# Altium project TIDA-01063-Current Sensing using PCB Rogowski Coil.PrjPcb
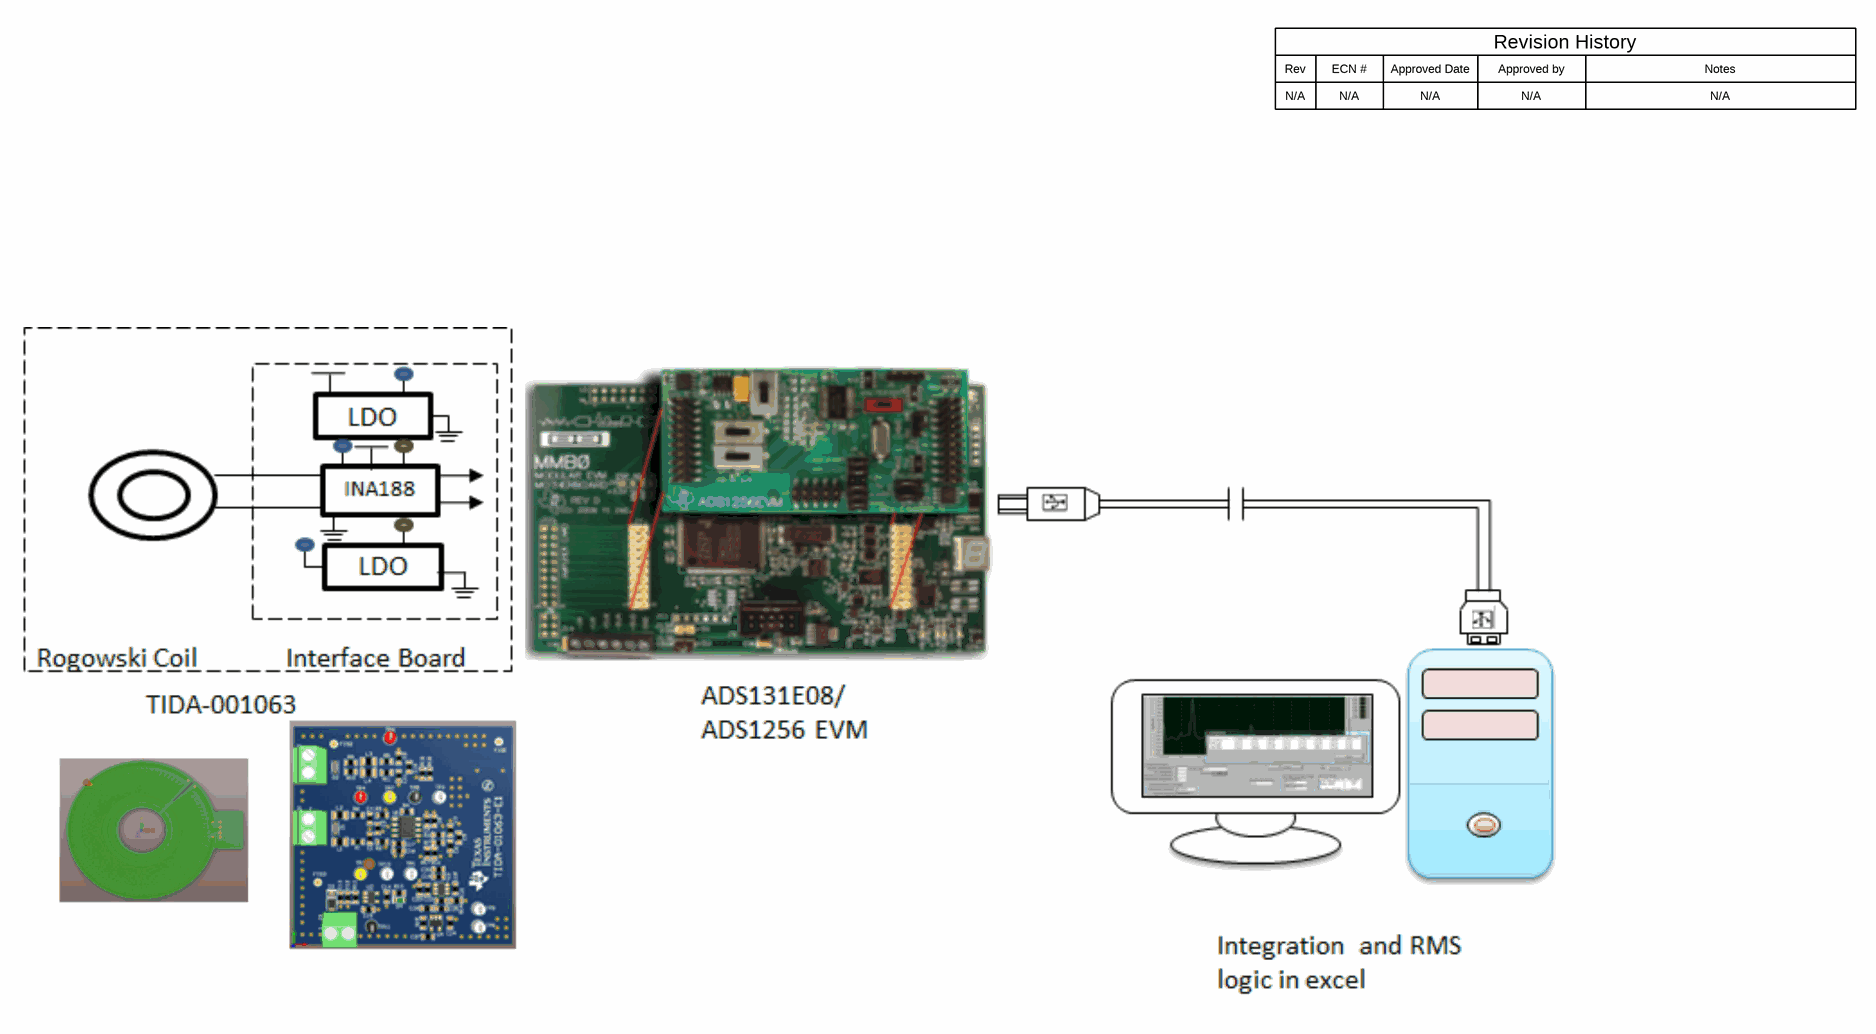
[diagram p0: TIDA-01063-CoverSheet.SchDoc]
TID: TIDA-01063; TechSupport: http://www.ti.com/support; SCH_Rev: E1; PRJ_Title: Current Sensing using PCB Rogowski Coil; PRJ_Number: TIDA-01063; PRJ_Engineer: Srinivasan Iyer; PRJ_Customer: Public Release; PCB_Rev: E1; PCB_Layout: Avinash N; EVM_Orderable: N/A; CopyrightYear: 2016
3 sheets, 86 parts. Net scope: global (net labels, ports and power ports of the same name join across sheets).
Board file: TIDA-01063-Interface Board.PcbDoc
Sheets:
  TIDA-01063-CoverSheet.SchDoc
  TIDA-01063-BlankSheet.SchDoc
  TIDA-01063_Hardware.SchDoc

## Sheet TIDA-01063-CoverSheet.SchDoc: Block Diagram
size 431 x 279 mm; Date: Not shown in title block; ApprovedBy: Not shown in title block; CheckedBy: Not shown in title block; Author: Not shown in title block; CompanyName: Not shown in title block; DrawnBy: Srinivasan Iyer; Engineer: Not shown in title block; Organization: Not shown in title block; Address1: Not shown in title block; Address2: Not shown in title block; Address3: Not shown in title block; Address4: Not shown in title block; DocumentNumber: 1; Revision: Use project parameter SCH_Rev; SheetNumber: 1; SheetTotal: 3; PageSetup: Record=PageOptions¦CenterHorizontal=True¦CenterVertical=True¦PrintScale=1.00¦XCorrection=1.00¦YCorrection=1.00¦PrintKind=0¦BorderSize=5000000¦LeftOffset=0¦BottomOffset=0¦Orientation=2¦PaperLength=1000¦PaperWidth=1000¦Scale=100¦PaperSource=15¦PrintQuality=600¦MediaType=1¦DitherType=10¦PaperKind=Letter¦PrintScaleMode=1

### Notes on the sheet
- Rev
- N/A
- ECN #
- Approved Date
- Approved by
- Revision History
- Notes

## Sheet TIDA-01063-BlankSheet.SchDoc: PCB Rogowski Coil Amplifier
size 431 x 279 mm; Date: Not shown in title block; ApprovedBy: Not shown in title block; CheckedBy: Not shown in title block; Author: Not shown in title block; CompanyName: Not shown in title block; DrawnBy: Srinivasan Iyer; Engineer: Not shown in title block; Organization: Not shown in title block; Address1: Not shown in title block; Address2: Not shown in title block; Address3: Not shown in title block; Address4: Not shown in title block; DocumentNumber: 1; Revision: Use project parameter SCH_Rev; SheetNumber: 2; SheetTotal: 3; PageSetup: Record=PageOptions¦CenterHorizontal=True¦CenterVertical=True¦PrintScale=1.00¦XCorrection=1.00¦YCorrection=1.00¦PrintKind=0¦BorderSize=5000000¦LeftOffset=0¦BottomOffset=0¦Orientation=2¦PaperLength=1000¦PaperWidth=1000¦Scale=100¦PaperSource=15¦PrintQuality=600¦MediaType=1¦DitherType=10¦PaperKind=Letter¦PrintScaleMode=1
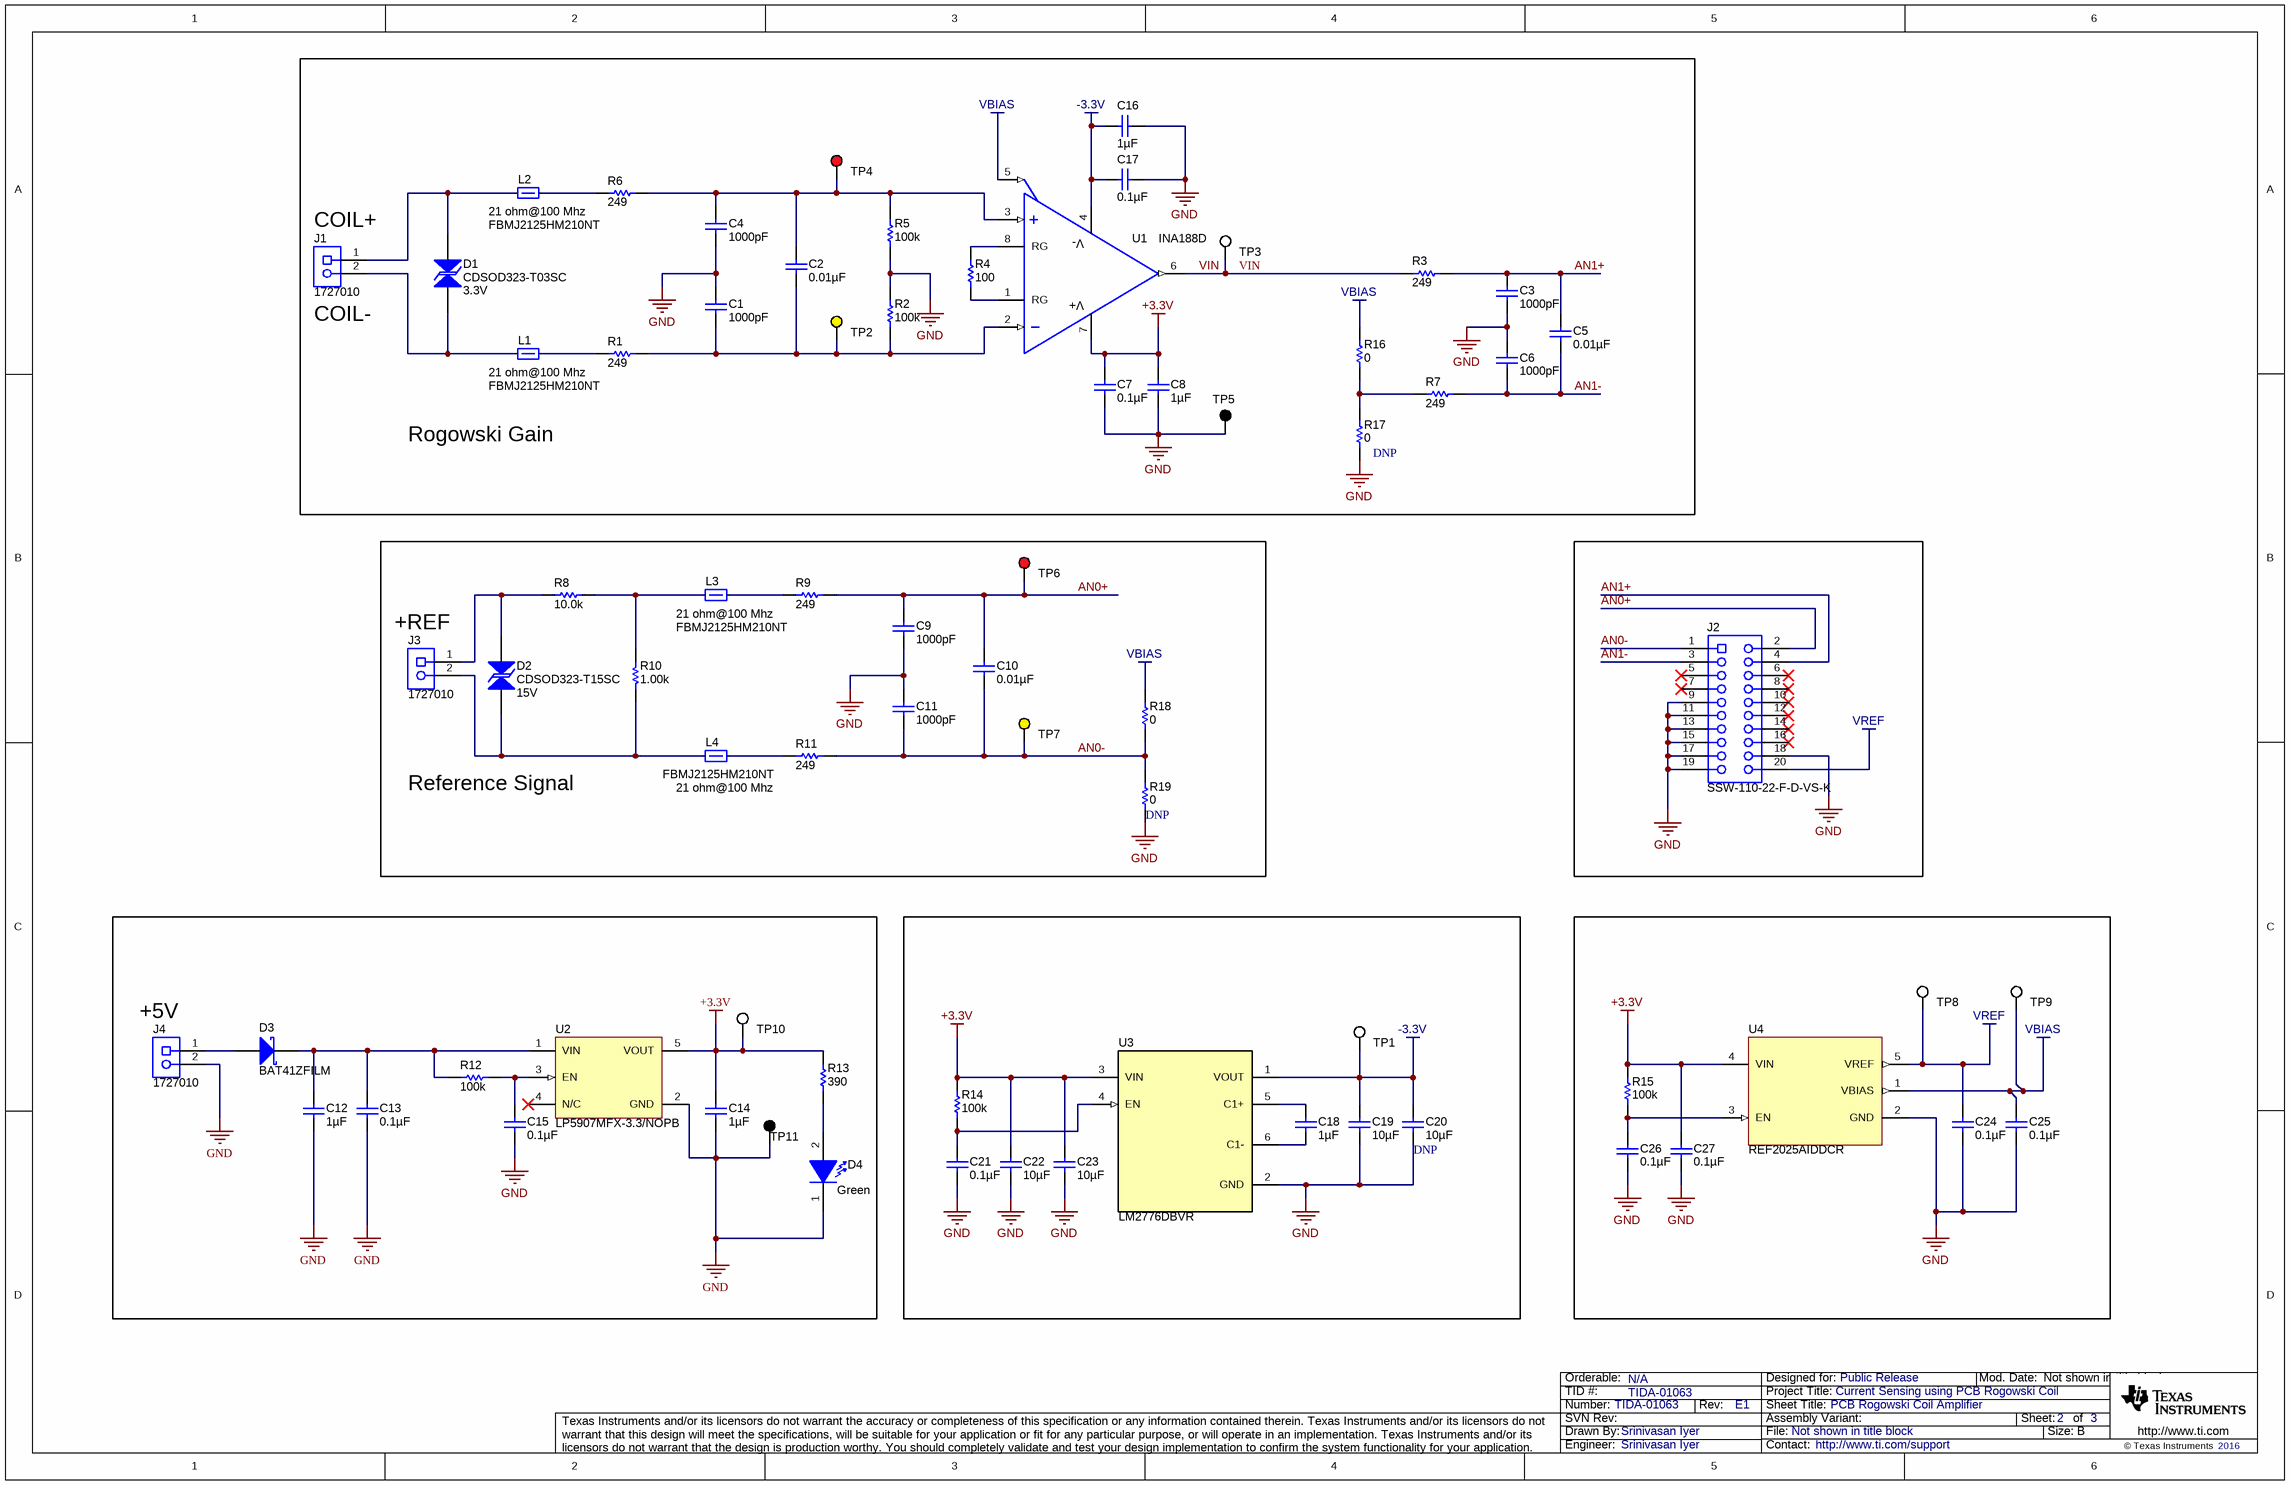
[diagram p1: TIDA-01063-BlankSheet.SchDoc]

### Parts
C1  ValueDisplayed: 1000pF  [0603]  (hidden comment: C0603X102K5RACTU)
C2  ValueDisplayed: 0.01µF  [0603]  (hidden comment: 06031C103JAT2A)
C3  ValueDisplayed: 1000pF  [0603]  (hidden comment: C0603X102K5RACTU)
C4  ValueDisplayed: 1000pF  [0603]  (hidden comment: C0603X102K5RACTU)
C5  ValueDisplayed: 0.01µF  [0603]  (hidden comment: 06031C103JAT2A)
C6  ValueDisplayed: 1000pF  [0603]  (hidden comment: C0603X102K5RACTU)
C7  ValueDisplayed: 0.1µF  [0603]  (hidden comment: CGA3E2X8R1E104K080AA)
C8  ValueDisplayed: 1µF  [0603]  (hidden comment: C1608X5R1C105K)
C9  ValueDisplayed: 1000pF  [0603]  (hidden comment: C0603X102K5RACTU)
C10  ValueDisplayed: 0.01µF  [0603]  (hidden comment: 06031C103JAT2A)
C11  ValueDisplayed: 1000pF  [0603]  (hidden comment: C0603X102K5RACTU)
C12  ValueDisplayed: 1µF  [0603]  (hidden comment: C1608X5R1C105K)
C13  ValueDisplayed: 0.1µF  [0603]  (hidden comment: CGA3E2X8R1E104K080AA)
C14  ValueDisplayed: 1µF  [0603]  (hidden comment: C1608X5R1C105K)
C15  ValueDisplayed: 0.1µF  [0603]  (hidden comment: CGA3E2X8R1E104K080AA)
C16  ValueDisplayed: 1µF  [0603]  (hidden comment: C1608X5R1C105K)
C17  ValueDisplayed: 0.1µF  [0603]  (hidden comment: CGA3E2X8R1E104K080AA)
C18  ValueDisplayed: 1µF  [0603]  (hidden comment: C1608X5R1C105K)
C19  ValueDisplayed: 10µF  [0603]  (hidden comment: C0603C106M9PACTU)
C20  ValueDisplayed: 10µF  [0603]  (hidden comment: C0603C106M9PACTU)
C21  ValueDisplayed: 0.1µF  [0603]  (hidden comment: CGA3E2X8R1E104K080AA)
C22  ValueDisplayed: 10µF  [0603]  (hidden comment: C0603C106M9PACTU)
C23  ValueDisplayed: 10µF  [0603]  (hidden comment: C0603C106M9PACTU)
C24  ValueDisplayed: 0.1µF  [0603]  (hidden comment: CGA3E2X8R1E104K080AA)
C25  ValueDisplayed: 0.1µF  [0603]  (hidden comment: CGA3E2X8R1E104K080AA)
C26  ValueDisplayed: 0.1µF  [0603]  (hidden comment: CGA3E2X8R1E104K080AA)
C27  ValueDisplayed: 0.1µF  [0603]  (hidden comment: CGA3E2X8R1E104K080AA)
D1  CDSOD323-T03SC  value 3.3V  [SOD-323-Bi]
D2  CDSOD323-T15SC  value 15V  [SOD-323-Bi]
D3  BAT41ZFILM  [SOD-123]
D4  value Green  [WL-SMCW_GREEN]  (hidden comment: 150060GS75000)
J1  1727010  [PhoenixConact_1727010]
J2  SSW-110-22-F-D-VS-K  [CONN_SSW-110-22-F-D-VS-K]
J3  1727010  [PhoenixConact_1727010]
J4  1727010  [PhoenixConact_1727010]
L1  value 21 ohm@100 Mhz  [0805_HV]  (hidden comment: FBMJ2125HM210NT)
L2  value 21 ohm@100 Mhz  [0805_HV]  (hidden comment: FBMJ2125HM210NT)
L3  value 21 ohm@100 Mhz  [0805_HV]  (hidden comment: FBMJ2125HM210NT)
L4  value 21 ohm@100 Mhz  [0805_HV]  (hidden comment: FBMJ2125HM210NT)
R1  ValueDisplayed: 249  [0603]  (hidden comment: RT0603BRD07249RL)
R2  ValueDisplayed: 100k  [0603]  (hidden comment: RC0603FR-07100KL)
R3  ValueDisplayed: 249  [0603]  (hidden comment: RT0603BRD07249RL)
R4  ValueDisplayed: 100  [0603]  (hidden comment: ERA-3AEB101V)
R5  ValueDisplayed: 100k  [0603]  (hidden comment: RC0603FR-07100KL)
R6  ValueDisplayed: 249  [0603]  (hidden comment: RT0603BRD07249RL)
R7  ValueDisplayed: 249  [0603]  (hidden comment: RT0603BRD07249RL)
R8  ValueDisplayed: 10.0k  [0603]  (hidden comment: RT0603DRE0710KL)
R9  ValueDisplayed: 249  [0603]  (hidden comment: RT0603BRD07249RL)
R10  ValueDisplayed: 1.00k  [0603]  (hidden comment: RT0603DRE071KL)
R11  ValueDisplayed: 249  [0603]  (hidden comment: RT0603BRD07249RL)
R12  ValueDisplayed: 100k  [0603]  (hidden comment: RC0603FR-07100KL)
R13  ValueDisplayed: 390  [0603]  (hidden comment: RC0603FR-07390RL)
R14  ValueDisplayed: 100k  [0603]  (hidden comment: RC0603FR-07100KL)
R15  ValueDisplayed: 100k  [0603]  (hidden comment: RC0603FR-07100KL)
R16  ValueDisplayed: 0  [0603]  (hidden comment: CRCW06030000Z0EA)
R17  ValueDisplayed: 0  [0603]  (hidden comment: CRCW06030000Z0EA)
R18  ValueDisplayed: 0  [0603]  (hidden comment: CRCW06030000Z0EA)
R19  ValueDisplayed: 0  [0603]  (hidden comment: CRCW06030000Z0EA)
TP1  5002  [Keystone5002]  (value not drawn)
TP2  5004  [Keystone5004]  (value not drawn)
TP3  5002  [Keystone5002]  (value not drawn)
TP4  5000  [Keystone5000]  (value not drawn)
TP5  5001  [Keystone5001]  (value not drawn)
TP6  5000  [Keystone5000]  (value not drawn)
TP7  5004  [Keystone5004]  (value not drawn)
TP8  5002  [Keystone5002]  (value not drawn)
TP9  5002  [Keystone5002]  (value not drawn)
TP10  5002  [Keystone5002]  (value not drawn)
TP11  5001  [Keystone5001]  (value not drawn)
U1  INA188D  [D0008A_N]
U2  LP5907MFX-3.3/NOPB  [DBV0005A_N]
U3  LM2776DBVR  [DBV0006A_N]
U4  REF2025AIDDCR  [DDC0005A_N]

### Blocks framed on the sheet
DNP: C1-C8 C16 C17 D1 J1 L1 L2 R1-R7 R16 R17 TP2-TP5 U1
DNP: C9-C11 D2 J3 L3 L4 R8-R11 R18 R19 TP6 TP7
DNP: C18-C23 R14 TP1 U3

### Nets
+3.3V: C7.1 C8.1 C14.1 C22.1 C23.1 C27.1 R13.2 R14.2 R15.2 TP10.1 U1.7(V+) U2.5(VOUT) U3.3(VIN) U4.4(VIN)
-3.3V: C16.1 C17.1 C19.1 C20.1 TP1.1 U1.4(V-) U3.1(VOUT)
GND: C1.1 C3.2 C4.2 C6.1 C7.2 C8.2 C9.2 C11.1 C12.2 C13.2 C14.2 C15.2 C16.2 C17.2 C19.2 C20.2 C21.2 C22.2 C23.2 C24.2 C25.2 C26.2 C27.2 D4.1(K) J2.9 J2.11 J2.13 J2.15 J2.17 J2.18 J2.19 J4.2 R2.2 R5.1 R17.2 R19.2 TP5.1 TP11.1 U2.2(GND) U3.2(GND) U4.2(GND)
VBIAS: C25.1 R16.1 R18.1 TP9.1 U1.5(REF) U4.1(VBIAS)
VREF: C24.1 J2.20 TP8.1 U4.5(VREF)
AN0+: C9.1 C10.1 J2.2 R9.2 TP6.1
AN0-: C10.2 C11.2 J2.1 R11.2 R18.2 R19.1 TP7.1
AN1+: C3.1 C5.1 J2.4 R3.2
AN1-: C5.2 C6.2 J2.3 R7.2
VIN: R3.1 TP3.1 U1.6(OUT)
NetC1_2: C1.2 C2.2 R1.2 R2.1 TP2.1 U1.2(IN-)
NetC2_1: C2.1 C4.1 R5.2 R6.2 TP4.1 U1.3(IN+)
NetC12_1: C12.1 C13.1 D3.1(K) R12.2 U2.1(VIN)
NetC15_1: C15.1 R12.1 U2.3(EN)
NetC18_1: C18.1 U3.5(C1+)
NetC18_2: C18.2 U3.6(C1-)
NetC21_1: C21.1 R14.1 U3.4(EN)
NetC26_1: C26.1 R15.1 U4.3(EN)
NetD1_1: D1.1 J1.2 L1.1
NetD1_2: D1.2 J1.1 L2.1
NetD2_1: D2.1 J3.2 L4.1 R10.2
NetD2_2: D2.2 J3.1 R8.2
NetD3_2: D3.2(A) J4.1
NetD4_2: D4.2(A) R13.1
NetL1_2: L1.2 R1.1
NetL2_2: L2.2 R6.1
NetL3_1: L3.1 R8.1 R10.1
NetL3_2: L3.2 R9.1
NetL4_2: L4.2 R11.1
NetR4_1: R4.1 U1.1(RG)
NetR4_2: R4.2 U1.8(RG)
NetR7_1: R7.1 R16.2 R17.1

Not connected (* = marked no-connect by the designer): J2 5* 6* 7* 8* 10* 12* 14* 16*; U2 4(N/C)*

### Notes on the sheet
- (near J1) COIL+
- (near J1) COIL-
- Rogowski Gain
- (near J3) +REF
- Reference Signal
- (near J4) +5V

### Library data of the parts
C1 C3 C4 C6 C9 C11 = C0603X102K5RACTU: CAP, CERM, 1000 pF, 50 V, +/- 10%, X7R, 0603; Manufacturer: Kemet; Polarized: N; CompType: Capacitor; Value: 1000pF; U/M: EA; Cap_F: 0.000000001; Tolerance_%: 10; Value1: Unknown; VDC_V: 50; Value2: 50V; TaMin_C: -55; TaMax_C: 125; AEC Category: Q200
C2 C5 C10 = 06031C103JAT2A: CAP, CERM, 0.01 µF, 100 V, +/- 5%, X7R, 0603; Manufacturer: AVX; Polarized: N; CompType: Capacitor; Value: 0.01uF; U/M: EA; Cap_F: 0.00000001; Tolerance_%: 5; ESR_ohm: 0.098; Value1: 0.098 ohm; VDC_V: 100; Value2: 100V; TaMin_C: -55; TaMax_C: 125; AEC Category: Q200
C7 C13 C15 C17 C21 C24-C27 = CGA3E2X8R1E104K080AA: CAP, CERM, 0.1 µF, 25 V, +/- 10%, X8R, AEC-Q200 Grade 0, 0603; Manufacturer: TDK; Polarized: N; CompType: Capacitor; Value: 0.1uF; U/M: EA; Cap_F: 0.0000001; Tolerance_%: 10; Value1: Unknown; VDC_V: 25; Value2: 25V; TaMin_C: -55; TaMax_C: 150; AEC Category: Q200; AEC Qualified: Y; AEC Grade: 0
C8 C12 C14 C16 C18 = C1608X5R1C105K: CAP, CERM, 1 µF, 16 V, +/- 10%, X5R, 0603; Manufacturer: TDK; Polarized: N; CompType: Capacitor; Value: 1uF; U/M: EA; Cap_F: 0.000001; Tolerance_%: 10; ESR_ohm: 0.0057; Value1: 0.0057 ohm; VDC_V: 16; Value2: 16V; TaMin_C: -55; TaMax_C: 85; AEC Category: Q200
C19 C20 C22 C23 = C0603C106M9PACTU: CAP, CERM, 10 µF, 6.3 V, +/- 20%, X5R, 0603; Manufacturer: Kemet; Polarized: N; CompType: Capacitor; Value: 10uF; U/M: EA; Cap_F: 0.00001; Tolerance_%: 20; ESR_ohm: 0.004; Value1: 0.004 ohm; VDC_V: 6.3; Value2: 6.3V; IRMS_A: 8.9; TaMin_C: -55; TaMax_C: 85; AEC Category: Q200
D1 = CDSOD323-T03SC: Diode, TVS, Bi, 3.3 V, 400 W, SOD323, 2-Leads, Body 1.9x1.45mm, No Polarity Mark; Manufacturer: Bourns; U/M: EA; Power_W: 400; Vr_V: 3.3; Value1: 400W; AEC Category: Q101; AEC Qualified: N
D2 = CDSOD323-T15SC: Diode, TVS, Bi, 15 V, 400 W, SOD323, 2-Leads, Body 1.9x1.45mm, No Polarity Mark; Manufacturer: Bourns; U/M: EA; Power_W: 400; Vr_V: 15; Value1: 400W; AEC Category: Q101
D3 = BAT41ZFILM: Diode, Schottky, 100 V, 0.2 A, SOD-123; Manufacturer: STMicroelectronics; U/M: EA; Vf_V: 1; Value: 100V; Value1: 0.2A; Value2: 1V; Io_A: 0.2; Vr_V: 100; TJmax_C: 150; AEC Category: Q101
D4 = 150060GS75000: LED, Green, SMD; Manufacturer: Wurth Elektronik; Type: InGaN; Vf_V: 3.2; Value2: 3.2V; Io_A: 0.02; Tjmax_C: 85; Value1: W; Angle: 140; U/M: EA
J1 J3 J4 = 1727010: Conn Term Block, 2POS, 3.81mm, TH; Manufacturer: Phoenix Contact; SymbolCreator: a0412235; CompType: Terminal Block; U/M: EA; Value: 2x1
J2 = SSW-110-22-F-D-VS-K: Connector, Receptacle, 100mil, 10x2, Gold plated, SMD; Manufacturer: Samtec; SymbolCreator: a0412235; U/M: EA
L1-L4 = FBMJ2125HM210NT: Ferrite Bead, 21 ohm @ 100 MHz, 6 A, 0805; Manufacturer: Taiyo Yuden; Imax_A: 6; DCR_ohm: 0.004; Value1: 0.004 ohm; Value2: 6A; ZTyp@100MHz_Ohm: 21
R1 R3 R6 R7 R9 R11 = RT0603BRD07249RL: RES, 249, 0.1%, 0.1 W, 0603; Manufacturer: Yageo America; CompType: Resistor; Value: 249; Value_Code: 249R; Tolerance_%: 0.1; Value2: 0.1W; VDC_V: 75; TempCo: 25 ppm/C; EIA_Code: E192; U/M: EA; AEC Category: Q200
R2 R5 R12 R14 R15 = RC0603FR-07100KL: RES, 100 k, 1%, 0.1 W, 0603; Manufacturer: Yageo America; CompType: Resistor; Value: 100k; Res_ohm: 100000; Tolerance_%: 1; Power_W: 0.1; Value2: 0.1W; VDC_V: 150; TempCo: 200 ppm/C; EIA_Code: E96; U/M: EA; AEC Category: Q200
R4 = ERA-3AEB101V: RES, 100, 0.1%, 0.1 W, AEC-Q200 Grade 0, 0603; Manufacturer: Panasonic; CompType: Resistor; Value: 100; Value_Code: 100R; Tolerance_%: 0.1; Value2: 0.1W; VDC_V: 75; TempCo: 25 ppm/C; EIA_Code: E192; U/M: EA; AEC Category: Q200; AEC Qualified: Y; AEC Grade: 0
R8 = RT0603DRE0710KL: RES, 10.0 k, 0.5%, 0.1 W, 0603; Manufacturer: Yageo America; CompType: Resistor; Value: 10.0k; Res_ohm: 10000; Value_Code: 10k0; Tolerance_%: 0.5; Power_W: 0.1; Value2: 0.1W; VDC_V: 75; TempCo: 50 ppm/C; EIA_Code: E192; U/M: EA; AEC Category: Q200
R10 = RT0603DRE071KL: RES, 1.00 k, 0.5%, 0.1 W, 0603; Manufacturer: Yageo America; CompType: Resistor; Value: 1.00k; Res_ohm: 1000; Value_Code: 1k00; Tolerance_%: 0.5; Power_W: 0.1; Value2: 0.1W; VDC_V: 75; TempCo: 50 ppm/C; EIA_Code: E192; U/M: EA; AEC Category: Q200
R13 = RC0603FR-07390RL: RES, 390, 1%, 0.1 W, 0603; Manufacturer: Yageo America; CompType: Resistor; Value: 390; Value_Code: 390R; Tolerance_%: 1; Power_W: 0.1; Value2: 0.1W; VDC_V: 150; TempCo: 200 ppm/C; U/M: EA; AEC Category: Q200
R16-R19 = CRCW06030000Z0EA: RES, 0, 5%, 0.1 W, 0603; Manufacturer: Vishay-Dale; CompType: Resistor; Value: 0; Value_Code: 0000; Tolerance_%: 5; Power_W: 0.1; Value2: 0.1W; VDC_V: 75; TempCo: 200 ppm/C; EIA_Code: E24; U/M: EA; AEC Category: Q200
TP1 TP3 TP8-TP10 = 5002: Test Point, Miniature, White, TH; Manufacturer: Keystone; CompType: Test Point Loop; U/M: EA
TP2 TP7 = 5004: Test Point, Miniature, Yellow, TH; Manufacturer: Keystone; CompType: Test Point Loop; U/M: EA
TP4 TP6 = 5000: Test Point, Miniature, Red, TH; Manufacturer: Keystone; CompType: Test Point Loop; U/M: EA
TP5 TP11 = 5001: Test Point, Miniature, Black, TH; Manufacturer: Keystone; CompType: Test Point Loop; U/M: EA
U1 = INA188D: INA188 Precision, Zero-Drift, Rail-to-Rail Out, High Voltage Instrumentation Amplifier, D0008A; Manufacturer: Texas Instruments; SymbolCreator: Altium; CompType: IC; U/M: EA
U2 = LP5907MFX-3.3/NOPB: ULTRA LOW-NOISE, 250-mA LINEAR REGULATOR FOR RF AND ANALOG CIRCUITS REQUIRES NO BYPASS CAPACITOR, DBV0005A; Manufacturer: Texas Instruments; SymbolCreator: a0799628; CompType: IC; U/M: EA
U3 = LM2776DBVR: Switched Capacitor Inverter, DBV0006A; Alternate PartNumber: LM2776DBVT; Manufacturer: Texas Instruments; SymbolCreator: Altium; CompType: IC; U/M: EA
U4 = REF2030AIDDCR: Low-Drift, Low-Power, Dual-Output, VREF and VREF / 2 Voltage References, 3.0V, DDC0005A; Alternate PartNumber: REF2025AIDDCT; Manufacturer: Texas Instruments; SymbolCreator: a0799628; CompType: IC; U/M: EA

## Sheet TIDA-01063_Hardware.SchDoc: PCB Hardware
size 431 x 279 mm; Date: Not shown in title block; ApprovedBy: Not shown in title block; CheckedBy: Not shown in title block; Author: Not shown in title block; CompanyName: Not shown in title block; DrawnBy: Srinivasan Iyer; Engineer: Not shown in title block; Organization: Not shown in title block; Address1: Not shown in title block; Address2: Not shown in title block; Address3: Not shown in title block; Address4: Not shown in title block; DocumentNumber: 1; Revision: Use project parameter SCH_Rev; SheetNumber: 3; SheetTotal: 3; PageSetup: Record=PageOptions¦CenterHorizontal=True¦CenterVertical=True¦PrintScale=1.00¦XCorrection=1.00¦YCorrection=1.00¦PrintKind=0¦BorderSize=5000000¦LeftOffset=0¦BottomOffset=0¦Orientation=2¦PaperLength=1000¦PaperWidth=1000¦Scale=100¦PaperSource=15¦PrintQuality=600¦MediaType=1¦DitherType=10¦PaperKind=Letter¦PrintScaleMode=1
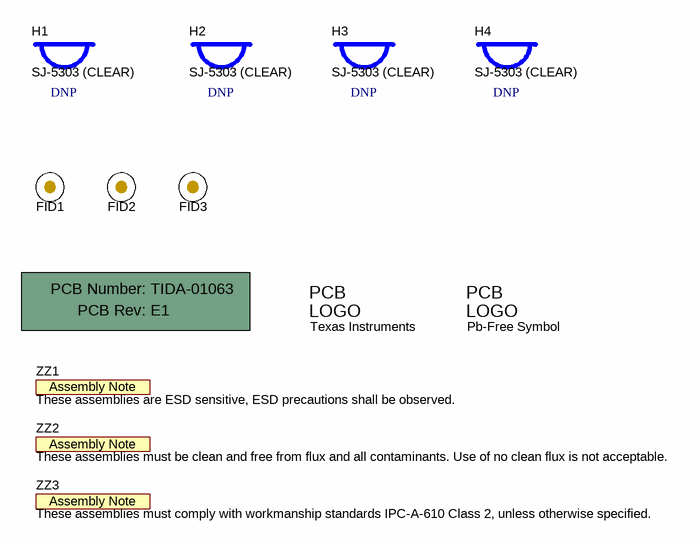
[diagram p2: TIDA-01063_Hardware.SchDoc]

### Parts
!PCB1  Printed Circuit Board  (value not drawn)  (mechanical)
FID1  Fiducial  [Fiducial10-20]  (value not drawn)
FID2  Fiducial  [Fiducial10-20]  (value not drawn)
FID3  Fiducial  [Fiducial10-20]  (value not drawn)
H1  SJ-5303 (CLEAR)  [Bumpon_SJ5003Transparent]
H2  SJ-5303 (CLEAR)  [Bumpon_SJ5003Transparent]
H3  SJ-5303 (CLEAR)  [Bumpon_SJ5003Transparent]
H4  SJ-5303 (CLEAR)  [Bumpon_SJ5003Transparent]
Logo1  Texas Instruments  [TI_Stacked_Overlay_Small]  (no BOM)
Logo2  Pb-Free Symbol  [Pb-Free_Overlay_Small]  (no BOM)
ZZ1  These assemblies are ESD sensitive, ESD precautions shall be observed.  [AssemblyNote]  (no BOM)
ZZ2  These assemblies must be clean and free from flux and all contaminants. Use of no clean flux is not acceptable.  [AssemblyNote]  (no BOM)
ZZ3  These assemblies must comply with workmanship standards IPC-A-610 Class 2, unless otherwise specified.  [AssemblyNote]  (no BOM)

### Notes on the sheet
- (near H1) DNP
- (near H2) DNP
- (near H3) DNP
- (near H4) DNP

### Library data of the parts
!PCB1 = PCB: Manufacturer: Any; PartNumber: TIDA-01063; SymbolCreator: a0412235
FID1-FID3 = Fiducial: Fiducial mark.  There is nothing to buy or mount.; SymbolCreator: codlsc
H1-H4 = SJ-5303 (CLEAR): Bumpon, Hemisphere, 0.44 X 0.20, Clear; Manufacturer: 3M; SymbolCreator: a0412235
Logo1 = TI_Logo: Texas Instrument Corporate Signature; SymbolCreator: codlsc
Logo2 = Pb-Free: SymbolCreator: a0412235
ZZ1-ZZ3 = AssemblyNote: SymbolCreator: codlsc

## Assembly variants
001: not fitted C20 D2 FID1 FID2 FID3 H1 H2 H3 H4 R17 R19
